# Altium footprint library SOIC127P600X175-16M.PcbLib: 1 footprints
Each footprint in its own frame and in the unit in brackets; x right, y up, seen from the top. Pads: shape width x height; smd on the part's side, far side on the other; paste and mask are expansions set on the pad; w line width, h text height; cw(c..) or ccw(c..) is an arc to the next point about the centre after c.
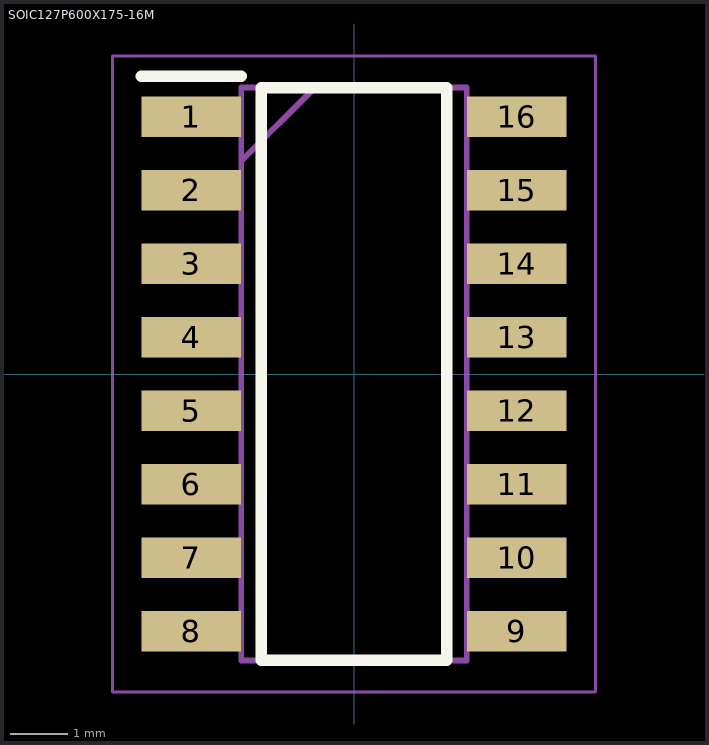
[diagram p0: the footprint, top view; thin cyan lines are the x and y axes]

## SOIC127P600X175-16M [mm]
pads (16):
  rect 1.725x0.7 smd: 1(-2.812,4.445) 2(-2.812,3.175) 3(-2.812,1.905) 4(-2.812,0.635) 5(-2.812,-0.635) 6(-2.812,-1.905) 7(-2.812,-3.175) 8(-2.812,-4.445) 9(2.812,-4.445) 10(2.812,-3.175) 11(2.812,-1.905) 12(2.812,-0.635) 13(2.812,0.635) 14(2.812,1.905) 15(2.812,3.175) 16(2.812,4.445)
Top Overlay:
  lines w0.2: -3.675,5.145 -1.95,5.145 ; -1.6,-4.95 1.6,-4.95 1.6,4.95 -1.6,4.95 -1.6,-4.95
Mechanical 15:
  lines w0.1: -1.95,3.68 -0.68,4.95 ; -1.95,-4.95 1.95,-4.95 1.95,4.95 -1.95,4.95 -1.95,-4.95
Mechanical 20:
  lines w0.05: -4.175,-5.5 4.175,-5.5 4.175,5.5 -4.175,5.5 -4.175,-5.5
